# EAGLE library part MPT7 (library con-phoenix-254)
PHOENIX CONNECTOR
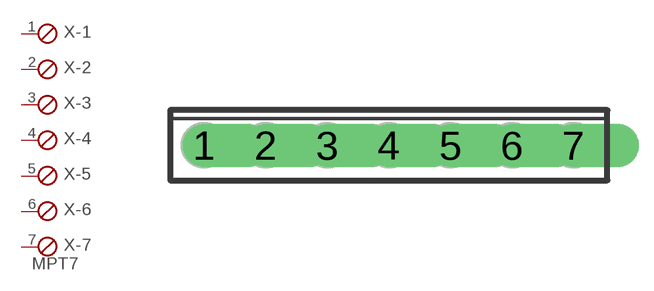
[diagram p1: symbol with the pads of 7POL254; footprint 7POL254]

Designator prefix X; gates -1=SKB -2=SKB -3=SKB -4=SKB -5=SKB -6=SKB -7=SKBV

## MPT7  [7POL254]
1  -1:1  pas
2  -2:1  pas
3  -3:1  pas
4  -4:1  pas
5  -5:1  pas
6  -6:1  pas
7  -7:1  pas

## Footprint 7POL254 (pad centres in mm)
PHOENIX CONNECTOR
drill 1.2 offset: 1 -7.62,0; 2 -5.08,0; 3 -2.54,0; 4 0,0; 5 2.54,0; 6 5.08,0; 7 7.62,0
